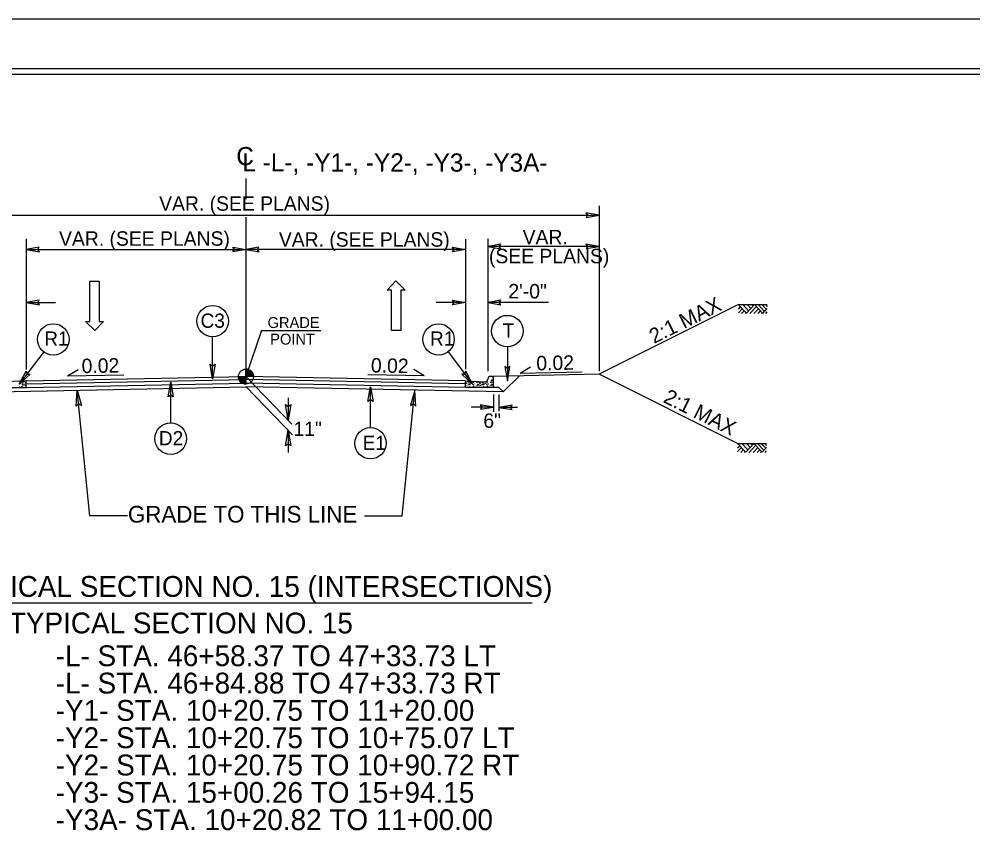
# Model space of a CAD drawing. Extents: x 1904401 to 1905163, y 193929 to 194736.
# Drawn here: x 1904883.7 to 1904969.4, y 194169.2 to 194243.4 of the extents above; entities that cross this region are included whole.
import ezdxf

# ---------------------------------------------------------------- set-up
doc = ezdxf.new("R2010")
doc.units = 0
for name, color, linetype in [('Default', 7, 'Continuous'), ('Old_Level_1', 7, 'Continuous'), ('Old_Level_11', 7, 'Continuous'), ('Old_Level_20', 7, 'Continuous'), ('Old_Level_3', 7, 'Continuous'), ('Prop Dimension Text', 7, 'Continuous'), ('Prop Lane Arrow CELL', 7, 'Continuous'), ('Sheet Cutting Line CELL', 7, 'Continuous'), ('Sheet Plot Border Inside CELL', 7, 'Continuous'), ('Sheet Plot Border Outside CELL', 7, 'Continuous'), ('Sheet Typical CELL', 7, 'Continuous'), ('Typical Arrow Superelevation CELL', 7, 'Continuous'), ('Typical Berm CELL', 7, 'Continuous'), ('Typical Curb CELL', 7, 'Continuous'), ('Typical Hinge Slope Arterial CELL', 7, 'Continuous'), ('Typical Pavement Slope CELL', 7, 'Continuous'), ('Typical Terminator CELL', 7, 'Continuous'), ('Typical Text Centerline CELL', 7, 'Continuous')]:
    doc.layers.add(name, color=color, linetype=linetype)

# ---------------------------------------------------------------- blocks, each defined once
blk = doc.blocks.new('TERMINATOR')
at = {"layer": 'Typical Terminator CELL'}
blk.add_lwpolyline([(-0.469, 0.081), (0, 0), (-0.471, -0.083), (-0.411, 0)], close=True, dxfattribs=at)

msp = doc.modelspace()

# ---------------------------------------------------------------- linework, layer by layer
at = {"layer": 'Default'}
msp.add_line((1904923.799, 194223.641), (1904923.799, 194211.943), dxfattribs=at)
at = {"layer": 'Old_Level_1'}
for p, q in [((1904872.299, 194225.805), (1904935.799, 194225.805)), ((1904884.299, 194222.713), (1904904.049, 194222.713)), ((1904923.799, 194222.713), (1904904.049, 194222.713)), ((1904935.799, 194222.993), (1904925.799, 194222.993)), ((1904884.299, 194217.947), (1904886.939, 194217.947)), ((1904923.799, 194217.947), (1904921.159, 194217.947)), ((1904931.245, 194217.947), (1904925.799, 194217.947)), ((1904948.319, 194217.753), (1904949.043, 194216.974)), ((1904948.319, 194217.352), (1904948.505, 194217.552)), ((1904948.319, 194217.019), (1904948.661, 194217.385)), ((1904948.71, 194217.761), (1904949.243, 194217.188)), ((1904949.043, 194216.974), (1904949.774, 194217.76)), ((1904949.108, 194217.761), (1904949.441, 194217.402)), ((1904949.353, 194216.956), (1904949.939, 194217.584)), ((1904949.51, 194217.761), (1904949.643, 194217.618)), ((1904949.723, 194216.956), (1904950.123, 194217.385)), ((1904949.774, 194217.76), (1904950.515, 194216.964)), ((1904950.096, 194217.761), (1904950.676, 194217.138)), ((1904950.429, 194217.761), (1904950.843, 194217.317)), ((1904950.515, 194216.964), (1904950.919, 194217.399)), ((1904950.749, 194217.761), (1904950.919, 194217.578)), ((1904948.607, 194216.956), (1904948.834, 194217.199)), ((1904948.918, 194216.956), (1904948.989, 194217.032)), ((1904950.089, 194216.956), (1904950.306, 194217.189)), ((1904950.384, 194216.956), (1904950.453, 194217.03)), ((1904950.785, 194216.956), (1904950.919, 194217.099)), ((1904903.374, 194211.282), (1904904.049, 194211.282)), ((1904904.047, 194210.607), (1904904.049, 194211.282)), ((1904904.049, 194211.282), (1904904.047, 194210.607)), ((1904904.049, 194211.282), (1904904.049, 194211.957)), ((1904904.724, 194211.282), (1904904.049, 194211.282)), ((1904904.049, 194211.282), (1904908.182, 194207.012)), ((1904904.067, 194210.365), (1904908.239, 194206.055)), ((1904907.844, 194209.361), (1904907.844, 194207.361)), ((1904907.839, 194206.469), (1904907.839, 194204.469)), ((1904948.252, 194205.267), (1904948.976, 194204.488)), ((1904948.252, 194204.866), (1904948.438, 194205.066)), ((1904948.252, 194204.533), (1904948.594, 194204.899)), ((1904948.54, 194204.47), (1904948.767, 194204.713)), ((1904948.643, 194205.275), (1904949.176, 194204.702)), ((1904948.851, 194204.47), (1904948.922, 194204.546)), ((1904948.976, 194204.488), (1904949.707, 194205.274)), ((1904949.041, 194205.275), (1904949.374, 194204.916)), ((1904949.286, 194204.47), (1904949.872, 194205.098)), ((1904949.443, 194205.275), (1904949.576, 194205.132)), ((1904949.656, 194204.47), (1904950.056, 194204.899)), ((1904949.707, 194205.274), (1904950.448, 194204.478)), ((1904950.022, 194204.47), (1904950.239, 194204.703)), ((1904950.029, 194205.275), (1904950.609, 194204.652)), ((1904950.317, 194204.47), (1904950.386, 194204.544)), ((1904950.362, 194205.275), (1904950.776, 194204.831)), ((1904950.448, 194204.478), (1904950.852, 194204.913)), ((1904950.682, 194205.275), (1904950.852, 194205.092)), ((1904950.718, 194204.47), (1904950.852, 194204.613)), ((1904877.386, 194190.926), (1904929.779, 194190.926))]:
    msp.add_line(p, q, dxfattribs=at)
for points in [[(1904948.319, 194217.761), (1904950.919, 194217.761)], [(1904903.377, 194211.282), (1904903.377, 194211.208)], [(1904903.39, 194211.282), (1904903.39, 194211.129)], [(1904903.404, 194211.282), (1904903.404, 194211.081)], [(1904903.417, 194211.282), (1904903.417, 194211.04)], [(1904903.431, 194211.282), (1904903.431, 194211.009)], [(1904903.444, 194211.282), (1904903.444, 194210.98)], [(1904903.458, 194211.282), (1904903.458, 194210.955)], [(1904903.471, 194211.282), (1904903.471, 194210.931)], [(1904903.485, 194211.282), (1904903.485, 194210.91)], [(1904903.498, 194211.282), (1904903.498, 194210.89)], [(1904903.512, 194211.282), (1904903.512, 194210.872)], [(1904903.525, 194211.282), (1904903.525, 194210.856)], [(1904903.539, 194211.282), (1904903.539, 194210.839)], [(1904903.552, 194211.282), (1904903.552, 194210.824)], [(1904903.566, 194211.282), (1904903.566, 194210.809)], [(1904903.579, 194211.282), (1904903.579, 194210.796)], [(1904903.593, 194211.282), (1904903.593, 194210.784)], [(1904903.606, 194211.282), (1904903.606, 194210.772)], [(1904903.62, 194211.282), (1904903.62, 194210.76)], [(1904903.633, 194211.282), (1904903.633, 194210.749)], [(1904903.647, 194211.282), (1904903.647, 194210.739)], [(1904903.66, 194211.282), (1904903.66, 194210.73)], [(1904903.674, 194211.282), (1904903.674, 194210.721)], [(1904903.687, 194211.282), (1904903.687, 194210.712)], [(1904903.701, 194211.282), (1904903.701, 194210.703)], [(1904903.714, 194211.282), (1904903.714, 194210.695)], [(1904903.728, 194211.282), (1904903.728, 194210.688)], [(1904903.741, 194211.282), (1904903.741, 194210.68)], [(1904903.755, 194211.282), (1904903.755, 194210.674)], [(1904903.768, 194211.282), (1904903.768, 194210.668)], [(1904903.782, 194211.282), (1904903.782, 194210.662)], [(1904903.795, 194211.282), (1904903.795, 194210.656)], [(1904903.809, 194211.282), (1904903.809, 194210.65)], [(1904903.822, 194211.282), (1904903.822, 194210.646)], [(1904903.836, 194211.282), (1904903.836, 194210.641)], [(1904903.849, 194211.282), (1904903.849, 194210.637)], [(1904903.863, 194211.282), (1904903.863, 194210.634)], [(1904903.876, 194211.282), (1904903.876, 194210.629)], [(1904903.89, 194211.282), (1904903.89, 194210.626)], [(1904903.903, 194211.282), (1904903.903, 194210.623)], [(1904903.917, 194211.282), (1904903.917, 194210.62)], [(1904903.93, 194211.282), (1904903.93, 194210.617)], [(1904903.944, 194211.282), (1904903.944, 194210.616)], [(1904903.957, 194211.282), (1904903.957, 194210.613)], [(1904903.971, 194211.282), (1904903.971, 194210.611)], [(1904903.984, 194211.282), (1904903.984, 194210.61)], [(1904903.998, 194211.282), (1904903.998, 194210.608)], [(1904904.011, 194211.282), (1904904.011, 194210.608)], [(1904904.025, 194211.282), (1904904.025, 194210.607)], [(1904904.038, 194211.282), (1904904.038, 194210.607), (1904904.038, 194210.607)], [(1904904.055, 194211.957), (1904904.055, 194211.957), (1904904.055, 194211.282)], [(1904904.068, 194211.957), (1904904.068, 194211.282)], [(1904904.082, 194211.955), (1904904.082, 194211.282)], [(1904904.095, 194211.955), (1904904.095, 194211.282)], [(1904904.109, 194211.954), (1904904.109, 194211.282)], [(1904904.122, 194211.952), (1904904.122, 194211.282)], [(1904904.136, 194211.951), (1904904.136, 194211.282)], [(1904904.149, 194211.949), (1904904.149, 194211.282)], [(1904904.163, 194211.948), (1904904.163, 194211.282)], [(1904904.176, 194211.945), (1904904.176, 194211.282)], [(1904904.19, 194211.942), (1904904.19, 194211.282)], [(1904904.203, 194211.939), (1904904.203, 194211.282)], [(1904904.217, 194211.936), (1904904.217, 194211.282)], [(1904904.23, 194211.931), (1904904.23, 194211.282)], [(1904904.244, 194211.928), (1904904.244, 194211.282)], [(1904904.257, 194211.924), (1904904.257, 194211.282)], [(1904904.271, 194211.919), (1904904.271, 194211.282)], [(1904904.284, 194211.915), (1904904.284, 194211.282)], [(1904904.298, 194211.909), (1904904.298, 194211.282)], [(1904904.311, 194211.903), (1904904.311, 194211.282)], [(1904904.325, 194211.897), (1904904.325, 194211.282)], [(1904904.338, 194211.891), (1904904.338, 194211.282)], [(1904904.352, 194211.885), (1904904.352, 194211.282)], [(1904904.365, 194211.877), (1904904.365, 194211.282)], [(1904904.379, 194211.87), (1904904.379, 194211.282)], [(1904904.392, 194211.862), (1904904.392, 194211.282)], [(1904904.406, 194211.855), (1904904.406, 194211.282)], [(1904904.419, 194211.846), (1904904.419, 194211.282)], [(1904904.433, 194211.837), (1904904.433, 194211.282)], [(1904904.446, 194211.826), (1904904.446, 194211.282)], [(1904904.46, 194211.817), (1904904.46, 194211.282)], [(1904904.473, 194211.807), (1904904.473, 194211.282)], [(1904904.487, 194211.795), (1904904.487, 194211.282)], [(1904904.5, 194211.783), (1904904.5, 194211.282)], [(1904904.514, 194211.771), (1904904.514, 194211.282)], [(1904904.527, 194211.757), (1904904.527, 194211.282)], [(1904904.541, 194211.744), (1904904.541, 194211.282)], [(1904904.554, 194211.729), (1904904.554, 194211.282)], [(1904904.568, 194211.712), (1904904.568, 194211.282)], [(1904904.581, 194211.696), (1904904.581, 194211.282)], [(1904904.595, 194211.678), (1904904.595, 194211.282)], [(1904904.608, 194211.658), (1904904.608, 194211.282)], [(1904904.622, 194211.637), (1904904.622, 194211.282)], [(1904904.635, 194211.615), (1904904.635, 194211.282)], [(1904904.649, 194211.591), (1904904.649, 194211.282)], [(1904904.662, 194211.562), (1904904.662, 194211.282)], [(1904904.676, 194211.531), (1904904.676, 194211.282)], [(1904904.689, 194211.493), (1904904.689, 194211.282)], [(1904904.703, 194211.447), (1904904.703, 194211.282)], [(1904904.716, 194211.378), (1904904.716, 194211.282)], [(1904948.252, 194205.275), (1904950.852, 194205.275)]]:
    msp.add_lwpolyline(points, dxfattribs=at)
msp.add_circle((1904904.048, 194211.282), 0.675, dxfattribs=at)
for start, end in [(179.99048, 269.99048), (359.99048, 89.99048)]:
    msp.add_arc((1904904.048, 194211.282), 0.675, start, end, dxfattribs=at)
at = {"layer": 'Old_Level_11'}
for p, q in [((1904901.056, 194211.079), (1904901.056, 194214.858)), ((1904927.553, 194213.965), (1904927.553, 194210.874)), ((1904885.88, 194213.496), (1904883.669, 194210.587)), ((1904922.217, 194213.496), (1904924.429, 194210.587)), ((1904897.286, 194207.112), (1904897.286, 194210.767)), ((1904915.247, 194206.7), (1904915.247, 194210.354))]:
    msp.add_line(p, q, dxfattribs=at)
for points in [[(1904901.281, 194212.388), (1904901.056, 194211.079), (1904900.823, 194212.395), (1904901.056, 194212.228)], [(1904927.328, 194212.184), (1904927.553, 194210.874), (1904927.786, 194212.191), (1904927.553, 194212.023)], [(1904884.64, 194211.493), (1904883.669, 194210.587), (1904884.28, 194211.776), (1904884.364, 194211.501)], [(1904923.457, 194211.493), (1904924.429, 194210.587), (1904923.818, 194211.776), (1904923.734, 194211.501)], [(1904897.061, 194209.457), (1904897.286, 194210.767), (1904897.519, 194209.45), (1904897.286, 194209.617)], [(1904915.021, 194209.045), (1904915.247, 194210.354), (1904915.48, 194209.038), (1904915.247, 194209.205)]]:
    msp.add_lwpolyline(points, close=True, dxfattribs=at)
for centre in [(1904901.056, 194216.272), (1904927.553, 194215.379), (1904886.736, 194214.622), (1904921.362, 194214.622), (1904897.286, 194205.698), (1904915.247, 194205.286)]:
    msp.add_circle(centre, 1.414, dxfattribs=at)
at = {"layer": 'Old_Level_3'}
for q in [(1904904.049, 194211.282), (1904910.782, 194215.415)]:
    msp.add_line((1904905.436, 194215.415), q, dxfattribs=at)
at = {"layer": 'Prop Dimension Text'}
for p, q in [((1904935.799, 194226.633), (1904935.799, 194211.767)), ((1904884.299, 194223.686), (1904884.299, 194211.921)), ((1904925.799, 194223.686), (1904925.799, 194211.767)), ((1904885.049, 194222.713), (1904896.049, 194222.713)), ((1904923.049, 194222.713), (1904912.049, 194222.713))]:
    msp.add_line(p, q, dxfattribs=at)
at = {"layer": 'Prop Lane Arrow CELL'}
for p, q in [((1904890.011, 194219.864), (1904890.867, 194219.864)), ((1904890.011, 194216.233), (1904890.011, 194219.864)), ((1904890.867, 194219.864), (1904890.867, 194216.233)), ((1904916.735, 194219.066), (1904917.539, 194219.883)), ((1904917.539, 194219.883), (1904918.369, 194219.066)), ((1904917.124, 194219.066), (1904916.735, 194219.066)), ((1904917.124, 194215.435), (1904917.124, 194219.066)), ((1904918.369, 194219.066), (1904917.98, 194219.066)), ((1904917.98, 194219.066), (1904917.98, 194215.435)), ((1904890.452, 194215.416), (1904889.622, 194216.233)), ((1904889.622, 194216.233), (1904890.011, 194216.233)), ((1904891.256, 194216.233), (1904890.452, 194215.416)), ((1904890.867, 194216.233), (1904891.256, 194216.233)), ((1904917.98, 194215.435), (1904917.124, 194215.435)), ((1904890.005, 194198.76), (1904888.862, 194210.061)), ((1904918.093, 194198.76), (1904919.236, 194210.061)), ((1904926.298, 194209.663), (1904926.298, 194208.124)), ((1904926.798, 194209.662), (1904926.798, 194208.164)), ((1904926.298, 194208.546), (1904924.308, 194208.546)), ((1904928.47, 194208.518), (1904926.798, 194208.518)), ((1904893.404, 194198.76), (1904890.005, 194198.76)), ((1904914.694, 194198.76), (1904918.093, 194198.76))]:
    msp.add_line(p, q, dxfattribs=at)
at = {"layer": 'Sheet Cutting Line CELL'}
msp.add_line((1905047.492, 194243.443), (1904710.692, 194243.443), dxfattribs=at)
at = {"layer": 'Sheet Plot Border Inside CELL'}
msp.add_lwpolyline([(1905046.592, 194238.953), (1904713.292, 194238.953), (1904713.292, 194027.933), (1905046.592, 194027.933)], close=True, dxfattribs=at)
at = {"layer": 'Sheet Plot Border Outside CELL'}
msp.add_lwpolyline([(1905047.492, 194243.443), (1904710.692, 194243.443), (1904710.692, 194023.443), (1905047.492, 194023.443)], close=True, dxfattribs=at)
at = {"layer": 'Sheet Typical CELL'}
msp.add_lwpolyline([(1905044.092, 194238.443), (1904744.092, 194238.443), (1904744.092, 194028.443), (1905044.092, 194028.443)], close=True, dxfattribs=at)
at = {"layer": 'Typical Arrow Superelevation CELL'}
for p, q in [((1904928.692, 194211.598), (1904929.632, 194212.166)), ((1904888.014, 194211.351), (1904888.953, 194211.919)), ((1904888.014, 194211.351), (1904893.085, 194211.452)), ((1904920.084, 194211.351), (1904915.013, 194211.452)), ((1904920.084, 194211.351), (1904919.144, 194211.919)), ((1904928.692, 194211.598), (1904934.286, 194211.71))]:
    msp.add_line(p, q, dxfattribs=at)
at = {"layer": 'Typical Berm CELL'}
msp.add_line((1904935.799, 194211.501), (1904926.298, 194211.303), dxfattribs=at)
at = {"layer": 'Typical Curb CELL'}
for p, q in [((1904926.298, 194211.303), (1904926.038, 194211.303)), ((1904926.298, 194210.303), (1904926.298, 194211.303)), ((1904884.299, 194210.887), (1904882.549, 194210.814)), ((1904883.952, 194210.663), (1904883.918, 194210.549)), ((1904883.918, 194210.549), (1904884.039, 194210.543)), ((1904884.039, 194210.543), (1904883.952, 194210.663)), ((1904884.299, 194210.303), (1904884.299, 194210.887)), ((1904923.799, 194210.303), (1904923.799, 194210.887)), ((1904923.799, 194210.887), (1904925.549, 194210.814)), ((1904924.059, 194210.543), (1904924.146, 194210.663)), ((1904924.18, 194210.549), (1904924.059, 194210.543)), ((1904924.146, 194210.663), (1904924.18, 194210.549)), ((1904924.825, 194210.492), (1904924.887, 194210.606)), ((1904924.99, 194210.531), (1904924.825, 194210.492)), ((1904924.887, 194210.606), (1904924.99, 194210.531)), ((1904925.309, 194210.543), (1904925.394, 194210.663)), ((1904925.429, 194210.549), (1904925.309, 194210.543)), ((1904925.394, 194210.663), (1904925.429, 194210.549)), ((1904925.799, 194211.053), (1904925.799, 194211.064)), ((1904926.074, 194210.492), (1904926.136, 194210.606)), ((1904926.239, 194210.531), (1904926.074, 194210.492)), ((1904926.108, 194210.97), (1904926.125, 194210.879)), ((1904926.262, 194210.925), (1904926.108, 194210.97)), ((1904926.125, 194210.879), (1904926.262, 194210.925)), ((1904926.136, 194210.606), (1904926.239, 194210.531)), ((1904881.799, 194210.303), (1904884.299, 194210.303)), ((1904926.298, 194210.303), (1904923.799, 194210.303))]:
    msp.add_line(p, q, dxfattribs=at)
for centre in [(1904883.781, 194210.68), (1904883.81, 194210.782), (1904883.958, 194210.845), (1904884.004, 194210.743), (1904884.101, 194210.828), (1904884.129, 194210.543), (1904884.209, 194210.703), (1904884.225, 194210.498), (1904884.265, 194210.737), (1904884.282, 194210.64), (1904923.815, 194210.64), (1904923.833, 194210.737), (1904923.872, 194210.498), (1904923.889, 194210.703), (1904923.969, 194210.543), (1904923.997, 194210.828), (1904924.094, 194210.743), (1904924.14, 194210.845), (1904924.288, 194210.782), (1904924.317, 194210.68), (1904924.465, 194210.595), (1904924.494, 194210.766), (1904924.499, 194210.441), (1904924.511, 194210.816), (1904924.591, 194210.623), (1904924.768, 194210.788), (1904924.888, 194210.737), (1904925.065, 194210.64), (1904925.082, 194210.737), (1904925.122, 194210.498), (1904925.138, 194210.703), (1904925.218, 194210.543), (1904925.246, 194210.797), (1904925.343, 194210.743), (1904925.537, 194210.782), (1904925.566, 194210.68), (1904925.714, 194210.595), (1904925.743, 194210.766), (1904925.748, 194210.441), (1904925.76, 194210.816), (1904925.84, 194210.623), (1904926.017, 194210.788), (1904926.068, 194211.227), (1904926.137, 194210.737), (1904926.234, 194211.011), (1904926.285, 194211.193), (1904883.713, 194210.355), (1904883.918, 194210.378), (1904884.078, 194210.309), (1904884.288, 194210.332), (1904923.81, 194210.332), (1904924.02, 194210.309), (1904924.18, 194210.378), (1904924.385, 194210.355), (1904924.556, 194210.326), (1904924.733, 194210.389), (1904924.905, 194210.349), (1904925.059, 194210.332), (1904925.269, 194210.309), (1904925.429, 194210.378), (1904925.634, 194210.355), (1904925.806, 194210.326), (1904925.983, 194210.389), (1904926.154, 194210.349)]:
    msp.add_circle(centre, 0.00802, dxfattribs=at)
for centre, start, end in [((1904926.038, 194211.064), 90, 180), ((1904925.559, 194211.053), 267.61554, 0)]:
    msp.add_arc(centre, 0.24, start, end, dxfattribs=at)
at = {"layer": 'Typical Hinge Slope Arterial CELL'}
for p in [(1904948.319, 194217.761), (1904948.252, 194205.275)]:
    msp.add_line(p, (1904935.799, 194211.501), dxfattribs=at)
at = {"layer": 'Typical Pavement Slope CELL'}
for p, q in [((1904884.299, 194210.887), (1904904.049, 194211.282)), ((1904923.799, 194210.887), (1904904.049, 194211.282)), ((1904927.188, 194209.904), (1904928.636, 194211.352)), ((1904884.304, 194210.637), (1904904.054, 194211.032)), ((1904884.311, 194210.303), (1904904.061, 194210.698)), ((1904923.787, 194210.303), (1904904.037, 194210.698)), ((1904923.794, 194210.637), (1904904.044, 194211.032)), ((1904880.908, 194209.902), (1904904.067, 194210.365)), ((1904927.19, 194209.902), (1904904.031, 194210.365)), ((1904926.798, 194210.293), (1904926.298, 194210.303)), ((1904927.19, 194209.902), (1904926.798, 194210.293))]:
    msp.add_line(p, q, dxfattribs=at)
at = {"layer": 'Typical Terminator CELL'}
for points in [[(1904934.627, 194225.604), (1904935.799, 194225.805), (1904934.621, 194226.014), (1904934.77, 194225.805)], [(1904885.471, 194222.915), (1904884.299, 194222.713), (1904885.477, 194222.505), (1904885.327, 194222.713)], [(1904902.877, 194222.915), (1904904.049, 194222.713), (1904902.871, 194222.505), (1904903.02, 194222.713)], [(1904905.221, 194222.915), (1904904.049, 194222.713), (1904905.227, 194222.505), (1904905.077, 194222.713)], [(1904922.627, 194222.915), (1904923.799, 194222.713), (1904922.621, 194222.505), (1904922.77, 194222.713)], [(1904926.971, 194223.195), (1904925.799, 194222.993), (1904926.977, 194222.785), (1904926.827, 194222.993)], [(1904934.627, 194222.791), (1904935.799, 194222.993), (1904934.621, 194223.201), (1904934.77, 194222.993)], [(1904885.471, 194218.149), (1904884.299, 194217.947), (1904885.477, 194217.738), (1904885.327, 194217.947)], [(1904922.627, 194218.149), (1904923.799, 194217.947), (1904922.621, 194217.738), (1904922.77, 194217.947)], [(1904926.971, 194218.149), (1904925.799, 194217.947), (1904926.977, 194217.738), (1904926.827, 194217.947)], [(1904888.775, 194208.637), (1904888.862, 194210.061), (1904889.265, 194208.683), (1904888.997, 194208.834)], [(1904919.323, 194208.637), (1904919.236, 194210.061), (1904918.833, 194208.683), (1904919.101, 194208.834)], [(1904925.127, 194208.344), (1904926.298, 194208.546), (1904925.12, 194208.754), (1904925.27, 194208.546)], [(1904927.97, 194208.72), (1904926.798, 194208.518), (1904927.976, 194208.31), (1904927.827, 194208.518)]]:
    msp.add_lwpolyline(points, close=True, dxfattribs=at)
at = {"layer": 'Typical Text Centerline CELL'}
for p, q in [((1904904.049, 194229.088), (1904904.049, 194227.24)), ((1904904.049, 194225.634), (1904904.049, 194222.713)), ((1904904.049, 194222.713), (1904904.049, 194211.352))]:
    msp.add_line(p, q, dxfattribs=at)

# ---------------------------------------------------------------- block references
at = {"layer": 'Old_Level_1', "xscale": 3, "yscale": 3}
for p, rotation in [((1904907.844, 194207.361), -90), ((1904907.839, 194206.469), 90)]:
    msp.add_blockref('TERMINATOR', p, dxfattribs=dict(at, rotation=rotation))

# ---------------------------------------------------------------- texts
at = {"layer": 'Old_Level_1'}
for s, height, p in [('VAR. (SEE PLANS)', 1.3, (1904896.247, 194226.203)), ('VAR. (SEE PLANS)', 1.3, (1904887.245, 194223.051)), ('VAR. (SEE PLANS)', 1.3, (1904907.009, 194222.969)), ('VAR.', 1.3, (1904928.926, 194223.181)), ('(SEE PLANS)', 1.3, (1904925.895, 194221.477)), ('2\'-0" ', 1.3, (1904927.641, 194218.315)), ('6" ', 1.3, (1904925.393, 194206.672)), ('TYPICAL SECTION NO. 15 (INTERSECTIONS)', 1.875, (1904877.963, 194191.47))]:
    msp.add_text(s, height=height, dxfattribs=at).set_placement(p)
at = {"layer": 'Old_Level_11'}
for s, p in [('GRADE', (1904905.995, 194215.652)), ('POINT', (1904906.232, 194214.161))]:
    msp.add_text(s, height=0.984, dxfattribs=at).set_placement(p)
at = {"layer": 'Old_Level_20'}
for s, height, p in [('C3', 1.2792, (1904899.968, 194215.675)), ('T', 1.279, (1904927.124, 194214.782)), ('R1', 1.2792, (1904885.92, 194214.063)), ('R1', 1.2792, (1904920.596, 194214.063)), ('11"', 1.3, (1904908.323, 194205.934)), ('D2', 1.2792, (1904896.221, 194205.101)), ('E1', 1.2792, (1904914.538, 194204.689))]:
    msp.add_text(s, height=height, dxfattribs=at).set_placement(p)
at = {"layer": 'Prop Dimension Text'}
for rotation, p in [(1.1462, (1904930.167, 194211.836)), (1.1462, (1904889.289, 194211.587)), (358.8538, (1904915.276, 194211.658))]:
    msp.add_text('0.02', height=1.3, rotation=rotation, dxfattribs=at).set_placement(p)
at = {"layer": 'Prop Lane Arrow CELL'}
msp.add_text('GRADE TO THIS LINE', height=1.5, rotation=0.00016, dxfattribs=at).set_placement((1904893.44, 194198.153))
for s, p in [('USE TYPICAL SECTION NO. 15', (1904876.883, 194188.18)), ('-L- STA. 46+58.37 TO 47+33.73 LT', (1904886.949, 194185.235)), ('-L- STA. 46+84.88 TO 47+33.73 RT', (1904886.949, 194182.777)), ('-Y1- STA. 10+20.75 TO 11+20.00', (1904886.949, 194180.319)), ('-Y2- STA. 10+20.75 TO 10+75.07 LT', (1904886.949, 194177.861)), ('-Y2- STA. 10+20.75 TO 10+90.72 RT', (1904886.949, 194175.403)), ('-Y3- STA. 15+00.26 TO 15+94.15', (1904886.949, 194172.945)), ('-Y3A- STA. 10+20.82 TO 11+00.00', (1904886.949, 194170.487))]:
    msp.add_text(s, height=1.875, dxfattribs=at).set_placement(p)
at = {"layer": 'Typical Hinge Slope Arterial CELL'}
for rotation, p in [(26.56505, (1904940.734, 194214.208)), (333.43495, (1904941.48, 194209.021))]:
    msp.add_text('2:1 MAX', height=1.35, rotation=rotation, dxfattribs=at).set_placement(p)
at = {"layer": 'Typical Text Centerline CELL'}
msp.add_text('C', height=1.64, dxfattribs=at).set_placement((1904903.181, 194230.296))
msp.add_text('L -L-, -Y1-, -Y2-, -Y3-, -Y3A-', height=1.64109, rotation=359.9469, dxfattribs=at).set_placement((1904903.726, 194229.736))

doc.saveas('drawing.dxf')
